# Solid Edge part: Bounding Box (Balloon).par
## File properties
Title: bounding box
Author: hhakima
Template: Normal.par
Last saved by: hhakima
Revision: 2
Application: Solid Edge
Manager: cgrant
Company: ALTAIR
Accuracy: 0.990
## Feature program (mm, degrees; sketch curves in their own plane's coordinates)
sketch for "unnamed Protrusion 1" plane through (0, 0, 0) normal (0, 0, 1) x-axis (1, 0, 0)
  line (-44.4755, 0) -> (65.5245, 0)
  line (65.5245, 0) -> (65.5245, 60)
  line (65.5245, 60) -> (-44.4755, 60)
  line (-44.4755, 60) -> (-44.4755, 0)
extrude "unnamed Protrusion 1" add finite 60 along +normal
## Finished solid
Body 1: solid body, 6 faces, 12 edges, 8 vertices.
  Faces by surface: plane 6
  Edges by curve: line 12
Bounding box of the edges (mm): 110.000 x 60.000 x 60.000, from (-44.4755, 0, 0) to (65.5245, 60, 60).
Planar faces by outward normal: +x 1, +y 1, +z 1, -x 1, -y 1, -z 1
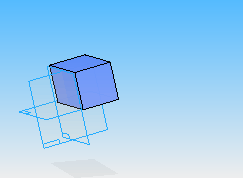
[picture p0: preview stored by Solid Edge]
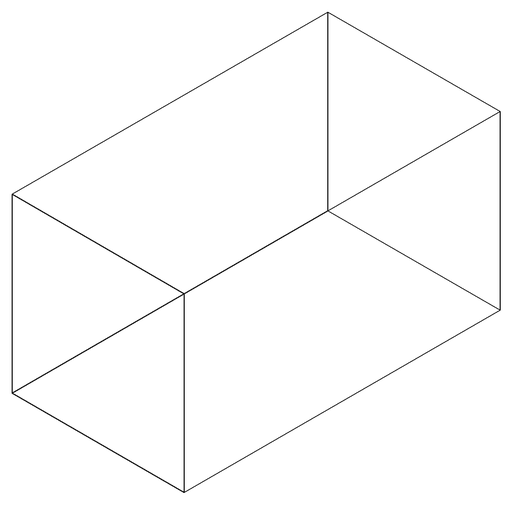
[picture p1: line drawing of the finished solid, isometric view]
